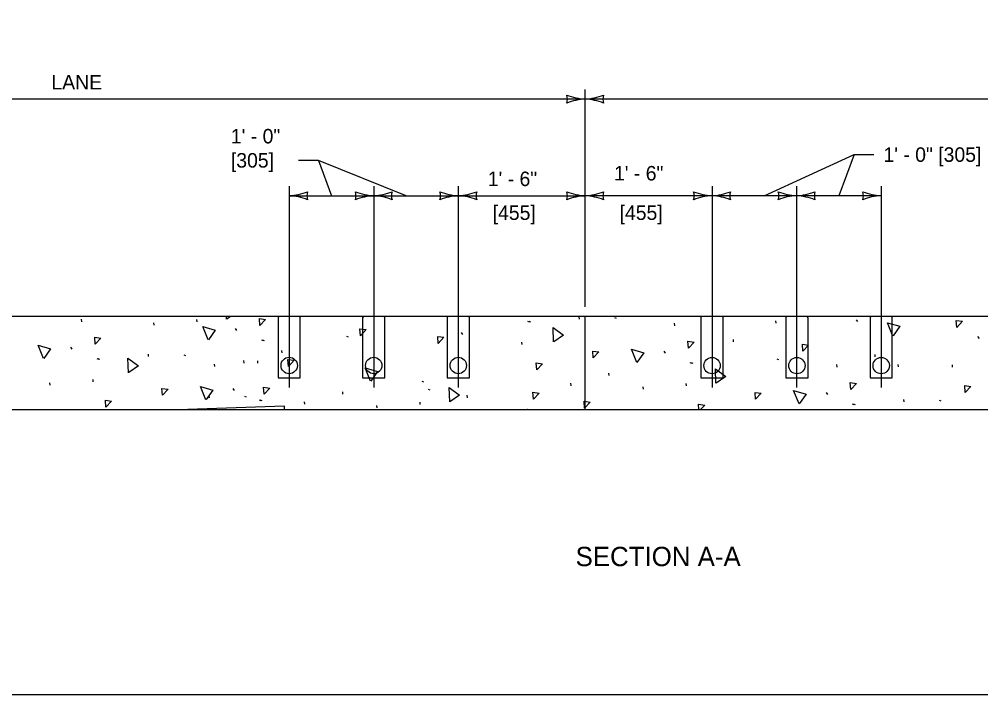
# Model space of a CAD drawing. Extents: x 49991.4 to 50021, y 49987.6 to 50011.4.
# Drawn here: x 50002.055 to 50006.035, y 49987.799 to 49990.594 of the extents above; entities that cross this region are included whole.
import ezdxf

# ---------------------------------------------------------------- set-up
doc = ezdxf.new("R2010")
doc.units = 0
for name, color, linetype in [('Level 1', 7, 'Continuous'), ('Level 2', 7, 'Continuous'), ('Level 3', 7, 'Continuous'), ('Level 4', 7, 'Continuous'), ('Level 5', 7, 'Continuous'), ('Level 9', 7, 'Continuous')]:
    doc.layers.add(name, color=color, linetype=linetype)

msp = doc.modelspace()

# ---------------------------------------------------------------- linework, layer by layer
at = {"layer": 'Level 1'}
for p, q in [((50008.5975, 49989.3638), (50000.1975, 49989.3638)), ((50004.3975, 49988.9788), (50004.3975, 49989.3638)), ((50000.1975, 49988.9788), (50008.5975, 49988.9788))]:
    msp.add_line(p, q, dxfattribs=at)
msp.add_lwpolyline([(49999.3835, 49998.9992), (50016.7501, 49998.9992), (50016.7501, 49987.7988), (49999.3835, 49987.7988)], close=True, dxfattribs=at)
at = {"layer": 'Level 3'}
for p, q in [((50004.3975, 49989.4038), (50004.3975, 49990.3038)), ((50004.3975, 49990.2638), (50000.1975, 49990.2638)), ((50008.5975, 49990.2638), (50004.3975, 49990.2638)), ((50005.51, 49990.0342), (50005.592, 49990.0342)), ((50003.2937, 49990.0104), (50003.2117, 49990.0104)), ((50003.1725, 49989.8638), (50003.5225, 49989.8638)), ((50003.5225, 49989.8638), (50003.8725, 49989.8638)), ((50003.8725, 49989.8638), (50004.3975, 49989.8638)), ((50004.9225, 49989.8638), (50004.3975, 49989.8638)), ((50005.2725, 49989.8638), (50004.9225, 49989.8638)), ((50005.6225, 49989.8638), (50005.2725, 49989.8638))]:
    msp.add_line(p, q, dxfattribs=at)
for points in [[(50005.1387, 49989.8638), (50005.51, 49990.0342), (50005.4475, 49989.8638)], [(50003.6562, 49989.8638), (50003.2937, 49990.0104), (50003.3475, 49989.8638)]]:
    msp.add_lwpolyline(points, dxfattribs=at)
for centre in [(50003.1725, 49989.1614), (50003.5225, 49989.1614), (50003.8725, 49989.1614), (50004.9225, 49989.1608), (50005.2736, 49989.1608), (50005.6225, 49989.1608)]:
    msp.add_circle(centre, 0.0338, dxfattribs=at)
for centre, radius, start, end in [((50004.4066, 49990.486), 0.2223, 247.456, 267.6395), ((50004.2692, 49990.2638), 0.0548, 342.1388, 17.8612), ((50004.409, 49990.0311), 0.233, 92.8273, 112.0772), ((50004.3883, 49990.486), 0.2223, 272.3605, 292.544), ((50004.386, 49990.0311), 0.233, 67.9228, 87.1727), ((50004.5257, 49990.2638), 0.0548, 162.1388, 197.8612), ((50003.161, 49990.0966), 0.233, 272.8273, 292.0772), ((50003.1633, 49989.6417), 0.2223, 67.456, 87.6395), ((50003.3007, 49989.8638), 0.0548, 162.1388, 197.8612), ((50003.5316, 49990.086), 0.2223, 247.456, 267.6395), ((50003.3942, 49989.8638), 0.0548, 342.1388, 17.8612), ((50003.534, 49989.6311), 0.233, 92.8273, 112.0772), ((50003.511, 49990.0966), 0.233, 272.8273, 292.0772), ((50003.5133, 49989.6417), 0.2223, 67.456, 87.6395), ((50003.6507, 49989.8638), 0.0548, 162.1388, 197.8612), ((50003.8816, 49990.086), 0.2223, 247.456, 267.6395), ((50003.7442, 49989.8638), 0.0548, 342.1388, 17.8612), ((50003.884, 49989.6311), 0.233, 92.8273, 112.0772), ((50003.861, 49990.0966), 0.233, 272.8273, 292.0772), ((50003.8633, 49989.6417), 0.2223, 67.456, 87.6395), ((50004.0007, 49989.8638), 0.0548, 162.1388, 197.8612), ((50004.4066, 49990.086), 0.2223, 247.456, 267.6395), ((50004.2692, 49989.8638), 0.0548, 342.1388, 17.8612), ((50004.409, 49989.6311), 0.233, 92.8273, 112.0772), ((50004.3883, 49990.086), 0.2223, 272.3605, 292.544), ((50004.386, 49989.6311), 0.233, 67.9228, 87.1727), ((50004.5257, 49989.8638), 0.0548, 162.1388, 197.8612), ((50004.7943, 49989.8638), 0.0548, 342.1388, 17.8612), ((50004.934, 49990.0966), 0.233, 247.9228, 267.1727), ((50004.9317, 49989.6417), 0.2223, 92.3605, 112.544), ((50004.9133, 49990.086), 0.2223, 272.3605, 292.544), ((50004.911, 49989.6311), 0.233, 67.9228, 87.1727), ((50005.0507, 49989.8638), 0.0548, 162.1388, 197.8612), ((50005.1443, 49989.8638), 0.0548, 342.1388, 17.8612), ((50005.284, 49990.0966), 0.233, 247.9228, 267.1727), ((50005.2817, 49989.6417), 0.2223, 92.3605, 112.544), ((50005.2633, 49990.086), 0.2223, 272.3605, 292.544), ((50005.261, 49989.6311), 0.233, 67.9228, 87.1727), ((50005.4007, 49989.8638), 0.0548, 162.1388, 197.8612), ((50005.4943, 49989.8638), 0.0548, 342.1388, 17.8612), ((50005.634, 49990.0966), 0.233, 247.9228, 267.1727), ((50005.6317, 49989.6417), 0.2223, 92.3605, 112.544)]:
    msp.add_arc(centre, radius, start, end, dxfattribs=at)
at = {"layer": 'Level 4'}
for p, q in [((50002.3138, 49989.3427), (50002.3127, 49989.3528)), ((50002.7915, 49989.342), (50002.7905, 49989.3521)), ((50004.1594, 49989.3453), (50004.1661, 49989.3419)), ((50004.1642, 49989.3453), (50004.1708, 49989.342)), ((50004.3739, 49989.3529), (50004.3728, 49989.3631)), ((50004.5192, 49989.3602), (50004.5259, 49989.3569)), ((50005.1874, 49989.3365), (50005.1863, 49989.3466)), ((50005.5183, 49989.3503), (50005.5238, 49989.3428)), ((50002.6132, 49989.3277), (50002.6121, 49989.3378)), ((50002.9495, 49989.3143), (50002.9551, 49989.3067)), ((50004.7687, 49989.326), (50004.7676, 49989.3362)), ((50003.0578, 49989.2681), (50003.0645, 49989.2648)), ((50003.0626, 49989.2681), (50003.0693, 49989.2648)), ((50003.4099, 49989.2831), (50003.4166, 49989.2798)), ((50003.8841, 49989.2976), (50003.8897, 49989.2901)), ((50005.0118, 49989.2592), (50005.0107, 49989.2693)), ((50006.0217, 49989.281), (50006.0273, 49989.2734)), ((50002.268, 49989.2371), (50002.2735, 49989.2296)), ((50004.1371, 49989.2482), (50004.136, 49989.2583)), ((50002.3763, 49989.1909), (50002.383, 49989.1876)), ((50002.3811, 49989.191), (50002.3878, 49989.1877)), ((50002.5908, 49989.1986), (50002.5897, 49989.2087)), ((50002.7361, 49989.2059), (50002.7428, 49989.2026)), ((50003.1432, 49989.2137), (50003.1421, 49989.2238)), ((50004.7228, 49989.2205), (50004.7284, 49989.2129)), ((50005.191, 49989.1893), (50005.1977, 49989.186)), ((50005.598, 49989.197), (50005.597, 49989.2071)), ((50002.8649, 49989.1567), (50002.8639, 49989.1669)), ((50002.9856, 49989.1717), (50002.9845, 49989.1819)), ((50003.0433, 49989.171), (50003.0422, 49989.1812)), ((50004.8311, 49989.1743), (50004.8378, 49989.171)), ((50004.8359, 49989.1743), (50004.8426, 49989.171)), ((50005.4404, 49989.155), (50005.4393, 49989.1652)), ((50005.6943, 49989.1559), (50005.6933, 49989.1661)), ((50005.9181, 49989.1544), (50005.9171, 49989.1645)), ((50004.4965, 49989.1198), (50004.4954, 49989.13)), ((50002.1834, 49989.0796), (50002.1823, 49989.0897)), ((50002.3618, 49989.0939), (50002.3607, 49989.104)), ((50002.9397, 49989.0661), (50002.9453, 49989.0586)), ((50003.7219, 49989.0971), (50003.7286, 49989.0938)), ((50004.3389, 49989.0779), (50004.3378, 49989.088)), ((50004.6382, 49989.0629), (50004.6372, 49989.0731)), ((50004.8166, 49989.0772), (50004.8155, 49989.0873)), ((50002.8426, 49989.0276), (50002.8415, 49989.0378)), ((50002.9879, 49989.035), (50002.9946, 49989.0316)), ((50003.395, 49989.0427), (50003.3939, 49989.0528)), ((50003.748, 49989.0639), (50003.7547, 49989.0606)), ((50003.9103, 49989.028), (50003.9093, 49989.0382)), ((50005.3946, 49989.0495), (50005.4001, 49989.0419)), ((50003.0481, 49989.02), (50003.0548, 49989.0167)), ((50003.0528, 49989.02), (50003.0595, 49989.0167)), ((50003.2373, 49989.0007), (50003.2363, 49989.0109)), ((50003.5367, 49988.9857), (50003.5356, 49988.9959)), ((50003.7151, 49989), (50003.714, 49989.0102)), ((50005.5029, 49989.0033), (50005.5096, 49989)), ((50005.5077, 49989.0033), (50005.5144, 49989)), ((50005.7174, 49989.011), (50005.7163, 49989.0211)), ((50005.8627, 49989.0183), (50005.8694, 49989.015))]:
    msp.add_line(p, q, dxfattribs=at)
for points in [[(50002.9135, 49989.3526), (50002.913, 49989.3638)], [(50002.9298, 49989.3638), (50002.9144, 49989.3531)], [(50003.0516, 49989.3267), (50003.0494, 49989.3553), (50003.0751, 49989.3522), (50003.0516, 49989.3267)], [(50003.7513, 49989.3636), (50003.7513, 49989.3638)], [(50003.7516, 49989.3638), (50003.7513, 49989.3636)], [(50005.9352, 49989.3192), (50005.933, 49989.3479), (50005.9587, 49989.3448), (50005.9352, 49989.3192)], [(50002.8377, 49989.2674), (50002.8152, 49989.3228), (50002.8665, 49989.3082), (50002.8384, 49989.2682)], [(50003.4675, 49989.2844), (50003.4653, 49989.3131), (50003.4911, 49989.31), (50003.4675, 49989.2844)], [(50004.2668, 49989.2588), (50004.2646, 49989.3185), (50004.3078, 49989.2872), (50004.2677, 49989.2593)], [(50005.6712, 49989.283), (50005.6487, 49989.3384), (50005.7, 49989.3238), (50005.6719, 49989.2838)], [(50002.37, 49989.2495), (50002.3678, 49989.2782), (50002.3935, 49989.2751), (50002.37, 49989.2495)], [(50003.7895, 49989.2531), (50003.7873, 49989.2817), (50003.813, 49989.2786), (50003.7895, 49989.2531)], [(50002.1562, 49989.1902), (50002.1337, 49989.2456), (50002.185, 49989.231), (50002.1568, 49989.191)], [(50004.611, 49989.1736), (50004.5885, 49989.229), (50004.6398, 49989.2143), (50004.6117, 49989.1744)], [(50004.8249, 49989.2329), (50004.8227, 49989.2615), (50004.8484, 49989.2584), (50004.8249, 49989.2329)], [(50005.2986, 49989.2203), (50005.2964, 49989.249), (50005.3222, 49989.2459), (50005.2986, 49989.2203)], [(50002.5074, 49989.1314), (50002.5052, 49989.1912), (50002.5483, 49989.1599), (50002.5083, 49989.1319)], [(50003.1695, 49989.1575), (50003.1673, 49989.1861), (50003.193, 49989.183), (50003.1695, 49989.1575)], [(50004.4308, 49989.1926), (50004.4286, 49989.2212), (50004.4543, 49989.2181), (50004.4308, 49989.1926)], [(50003.5095, 49989.0964), (50003.487, 49989.1518), (50003.5383, 49989.1372), (50003.5101, 49989.0972)], [(50004.1971, 49989.1432), (50004.1949, 49989.1718), (50004.2206, 49989.1687), (50004.1971, 49989.1432)], [(50004.9385, 49989.0878), (50004.9363, 49989.1475), (50004.9795, 49989.1162), (50004.9394, 49989.0883)], [(50002.6477, 49989.0383), (50002.6455, 49989.0669), (50002.6712, 49989.0638), (50002.6477, 49989.0383)], [(50002.8279, 49989.0193), (50002.8054, 49989.0746), (50002.8567, 49989.06), (50002.8286, 49989.0201)], [(50003.0685, 49989.0426), (50003.0663, 49989.0712), (50003.092, 49989.0681), (50003.0685, 49989.0426)], [(50003.837, 49989.0106), (50003.8348, 49989.0704), (50003.878, 49989.0391), (50003.8379, 49989.0111)], [(50005.4966, 49989.0619), (50005.4944, 49989.0905), (50005.5201, 49989.0874), (50005.4966, 49989.0619)], [(50005.9704, 49989.0493), (50005.9682, 49989.078), (50005.9939, 49989.0749), (50005.9704, 49989.0493)], [(50004.1835, 49989.0218), (50004.1813, 49989.0505), (50004.207, 49989.0474), (50004.1835, 49989.0218)], [(50005.1026, 49989.0216), (50005.1004, 49989.0503), (50005.1261, 49989.0472), (50005.1026, 49989.0216)], [(50005.2828, 49989.0026), (50005.2603, 49989.058), (50005.3116, 49989.0434), (50005.2834, 49989.0034)], [(50002.414, 49988.9889), (50002.4118, 49989.0175), (50002.4375, 49989.0144), (50002.414, 49988.9889)], [(50003.1538, 49988.9788), (50003.1532, 49988.9932), (50002.7531, 49988.9788)], [(50004.3951, 49988.9847), (50004.3929, 49989.0134), (50004.4186, 49989.0103), (50004.3951, 49988.9847)], [(50004.8683, 49988.9788), (50004.8667, 49989.0008), (50004.8924, 49988.9977), (50004.875, 49988.9788)], [(50004.1595, 49988.9788), (50004.1587, 49988.9808), (50004.1657, 49988.9788)]]:
    msp.add_lwpolyline(points, dxfattribs=at)
at = {"layer": 'Level 5'}
for p, q in [((50003.1725, 49989.9038), (50003.1725, 49989.0708)), ((50003.5225, 49989.9038), (50003.5225, 49989.0708)), ((50003.8725, 49989.9038), (50003.8725, 49989.0708)), ((50004.9225, 49989.9038), (50004.9225, 49989.0708)), ((50005.2725, 49989.9038), (50005.2725, 49989.0708)), ((50005.6225, 49989.9038), (50005.6225, 49989.0708))]:
    msp.add_line(p, q, dxfattribs=at)
at = {"layer": 'Level 9'}
for p, q in [((50003.1264, 49989.3586), (50003.1264, 49989.1908)), ((50003.2127, 49989.3644), (50003.1322, 49989.3644)), ((50003.2186, 49989.1908), (50003.2186, 49989.3586)), ((50003.4764, 49989.3586), (50003.4764, 49989.1908)), ((50003.5627, 49989.3644), (50003.4822, 49989.3644)), ((50003.5686, 49989.1908), (50003.5686, 49989.3586)), ((50003.8264, 49989.3586), (50003.8264, 49989.1908)), ((50003.9127, 49989.3644), (50003.8322, 49989.3644)), ((50003.9186, 49989.1908), (50003.9186, 49989.3586)), ((50004.8764, 49989.358), (50004.8764, 49989.1902)), ((50004.9627, 49989.3638), (50004.8822, 49989.3638)), ((50004.9686, 49989.1902), (50004.9686, 49989.358)), ((50005.2275, 49989.358), (50005.2275, 49989.1902)), ((50005.3139, 49989.3638), (50005.2333, 49989.3638)), ((50005.3197, 49989.1902), (50005.3197, 49989.358)), ((50005.5764, 49989.358), (50005.5764, 49989.1902)), ((50005.6627, 49989.3638), (50005.5822, 49989.3638)), ((50005.6686, 49989.1902), (50005.6686, 49989.358)), ((50003.1264, 49989.1908), (50003.1264, 49989.1103)), ((50003.2186, 49989.1103), (50003.2186, 49989.1908)), ((50003.4764, 49989.1908), (50003.4764, 49989.1103)), ((50003.5686, 49989.1103), (50003.5686, 49989.1908)), ((50003.8264, 49989.1908), (50003.8264, 49989.1103)), ((50003.9186, 49989.1103), (50003.9186, 49989.1908)), ((50004.8764, 49989.1902), (50004.8764, 49989.1097)), ((50004.9686, 49989.1097), (50004.9686, 49989.1902)), ((50005.2275, 49989.1902), (50005.2275, 49989.1097)), ((50005.3197, 49989.1097), (50005.3197, 49989.1902)), ((50005.5764, 49989.1902), (50005.5764, 49989.1097)), ((50005.6686, 49989.1097), (50005.6686, 49989.1902)), ((50003.1264, 49989.1103), (50003.2186, 49989.1103)), ((50003.4764, 49989.1103), (50003.5686, 49989.1103)), ((50003.8264, 49989.1103), (50003.9186, 49989.1103)), ((50004.8764, 49989.1097), (50004.9686, 49989.1097)), ((50005.2275, 49989.1097), (50005.3197, 49989.1097)), ((50005.5764, 49989.1097), (50005.6686, 49989.1097))]:
    msp.add_line(p, q, dxfattribs=at)
for centre, start, end in [((50003.1322, 49989.3586), 90, 180), ((50003.2127, 49989.3586), 0, 90), ((50003.4822, 49989.3586), 90, 180), ((50003.5627, 49989.3586), 0, 90), ((50003.8322, 49989.3586), 90, 180), ((50003.9127, 49989.3586), 0, 90), ((50004.8822, 49989.358), 90, 180), ((50004.9627, 49989.358), 0, 90), ((50005.2333, 49989.358), 90, 180), ((50005.3139, 49989.358), 0, 90), ((50005.5822, 49989.358), 90, 180), ((50005.6627, 49989.358), 0, 90)]:
    msp.add_arc(centre, 0.00583, start, end, dxfattribs=at)

# ---------------------------------------------------------------- texts
at = {"layer": 'Level 2'}
for s, height, p in [('LANE', 0.06, (50002.1885, 49990.3038)), ('1\' - 0"', 0.06, (50002.9313, 49990.0804)), ('1\' - 0" [305]', 0.06, (50005.632, 49990.0042)), ('[305]', 0.06, (50002.9313, 49989.9804)), ('1\' - 6"', 0.06, (50004.5168, 49989.927)), ('1\' - 6"', 0.06, (50003.9944, 49989.9038)), ('[455]', 0.06, (50004.0147, 49989.7638)), ('[455]', 0.06, (50004.5398, 49989.7638)), ('SECTION A-A', 0.08, (50004.3577, 49988.331))]:
    msp.add_text(s, height=height, dxfattribs=at).set_placement(p)

doc.saveas('drawing.dxf')
